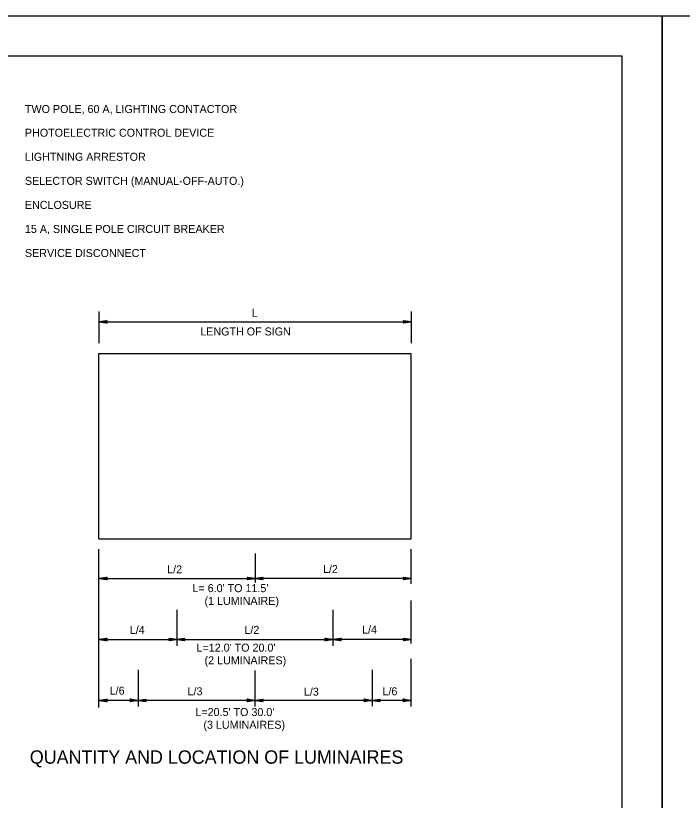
# Model space of a CAD drawing. Extents: x 36 to 2622, y -5330 to 219.
# Drawn here: x 1476.1 to 1725.4, y -4435.3 to -4141.8 of the extents above; entities that cross this region are included whole.
import ezdxf

# ---------------------------------------------------------------- set-up
doc = ezdxf.new("R2010")
doc.units = 0
for name, color, linetype in [('1', 7, 'Continuous'), ('2', 7, 'Continuous'), ('3', 7, 'Continuous'), ('PLT-BNDY', 7, 'Continuous')]:
    doc.layers.add(name, color=color, linetype=linetype)

# ---------------------------------------------------------------- blocks, each defined once
blk = doc.blocks.new('RARROW')
at = {"layer": '3'}
blk.add_lwpolyline([(-2.2695, 0.285), (-2.184875, 0.12075), (0, 0), (-2.2695, 0.285), (-2.38575, 0.384625), (0, 0), (-2.183125, -0.108), (-2.262875, -0.2705), (0, 0), (-2.38575, -0.379125), (-2.262875, -0.2705)], dxfattribs=at)

msp = doc.modelspace()

# ---------------------------------------------------------------- linework, layer by layer
at = {"layer": '1'}
for p in [(916.86, -4156.83), (1702.86, -4720.83)]:
    msp.add_line(p, (1702.86, -4156.83), dxfattribs=at)
at = {"layer": '2'}
for p, q in [((1507.23, -4252.45), (1507.23, -4264.33)), ((1623.98, -4252.45), (1623.98, -4264.33)), ((1507.23, -4256.33), (1623.98, -4256.33)), ((1507.23, -4337.58), (1507.23, -4268.2)), ((1507.23, -4268.2), (1623.98, -4268.2)), ((1623.98, -4337.58), (1623.98, -4268.2)), ((1507.23, -4337.58), (1623.98, -4337.58)), ((1507.23, -4400.58), (1507.23, -4341.45)), ((1565.61, -4343.08), (1565.61, -4353.82)), ((1623.98, -4354.33), (1623.98, -4341.45)), ((1507.23, -4352.33), (1565.61, -4352.33)), ((1623.98, -4352.33), (1565.61, -4352.33)), ((1623.98, -4376.7), (1623.98, -4360.64)), ((1536.36, -4364.08), (1536.36, -4377.58)), ((1594.73, -4364.08), (1594.73, -4377.58)), ((1507.23, -4375.2), (1536.36, -4375.2)), ((1536.36, -4375.2), (1594.73, -4375.2)), ((1623.98, -4375.2), (1594.73, -4375.2)), ((1623.98, -4400.2), (1623.98, -4382.41)), ((1521.86, -4386.58), (1521.86, -4400.2)), ((1565.61, -4400.2), (1565.61, -4386.83)), ((1609.36, -4386.58), (1609.36, -4400.08)), ((1521.86, -4397.95), (1507.23, -4397.95)), ((1565.61, -4397.95), (1521.86, -4397.95)), ((1609.36, -4397.95), (1565.61, -4397.95)), ((1623.98, -4397.95), (1609.36, -4397.95))]:
    msp.add_line(p, q, dxfattribs=at)
at = {"layer": 'PLT-BNDY'}
for points in [[(876.86, -4141.83), (1717.86, -4141.83), (1717.86, -4735.83), (876.86, -4735.83)], [(1717.86, -4141.83), (2558.86, -4141.83), (2558.86, -4735.83), (1717.86, -4735.83)]]:
    msp.add_lwpolyline(points, close=True, dxfattribs=at)

# ---------------------------------------------------------------- block references
at = {"layer": '2', "xscale": 1.2574347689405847, "yscale": 1.3092961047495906, "rotation": 180}
for p in [(1507.23, -4256.33), (1507.23, -4352.33), (1565.61, -4352.33), (1507.23, -4375.2), (1536.36, -4375.2), (1594.73, -4375.2), (1507.23, -4397.95), (1521.86, -4397.95), (1565.61, -4397.95), (1609.36, -4397.95)]:
    msp.add_blockref('RARROW', p, dxfattribs=at)
at = {"layer": '2', "xscale": 1.2574347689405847, "yscale": 1.3092961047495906}
for p in [(1623.98, -4256.33), (1565.61, -4352.33), (1623.98, -4352.33), (1536.36, -4375.2), (1594.73, -4375.2), (1623.98, -4375.2), (1521.86, -4397.95), (1565.61, -4397.95), (1609.36, -4397.95), (1623.98, -4397.95)]:
    msp.add_blockref('RARROW', p, dxfattribs=at)

# ---------------------------------------------------------------- texts
at = {"layer": '2'}
for s, height, p in [('TWO POLE, 60 A, LIGHTING CONTACTOR', 3, (1479.53, -4178.24)), ('PHOTOELECTRIC CONTROL DEVICE', 2.9955, (1479.53, -4187.11)), ('LIGHTNING ARRESTOR', 2.9955, (1479.53, -4196.11)), ('SELECTOR SWITCH (MANUAL-OFF-AUTO.)', 2.9955, (1479.53, -4205.11)), ('ENCLOSURE', 2.996, (1479.53, -4214.11)), ('15 A, SINGLE POLE CIRCUIT BREAKER', 3, (1479.53, -4223.11)), ('SERVICE DISCONNECT', 3, (1479.53, -4232.11)), ('L', 3, (1564.36, -4254.45)), ('LENGTH OF SIGN', 2.9955, (1545.11, -4261.45)), ('L/2 ', 2.996, (1532.73, -4350.45)), ('L/2 ', 2.996, (1590.98, -4350.33)), ("L= 6.0' TO 11.5'", 3, (1542.18, -4357.48)), ('(1 LUMINAIRE)', 3, (1546.68, -4362.23)), ('L/4', 2.996, (1518.73, -4373.08)), ('L/2 ', 2.996, (1561.61, -4373.08)), ('L/4', 2.996, (1605.61, -4372.95)), ("L=12.0' TO 20.0'", 3, (1543.7, -4379.73)), ('(2 LUMINAIRES)', 3, (1546.7, -4384.48)), ('L/6', 2.996, (1511.23, -4395.83)), ('L/3', 2.996, (1540.36, -4396.08)), ('L/3', 2.996, (1583.86, -4396.2)), ('L/6', 2.996, (1613.23, -4396.08)), ("L=20.5' TO 30.0'", 3, (1543.28, -4403.83)), ('(3 LUMINAIRES)', 3, (1546.28, -4408.58)), ('QUANTITY AND LOCATION OF LUMINAIRES', 5, (1481.36, -4421.66))]:
    msp.add_text(s, height=height, dxfattribs=at).set_placement(p)

doc.saveas('drawing.dxf')
